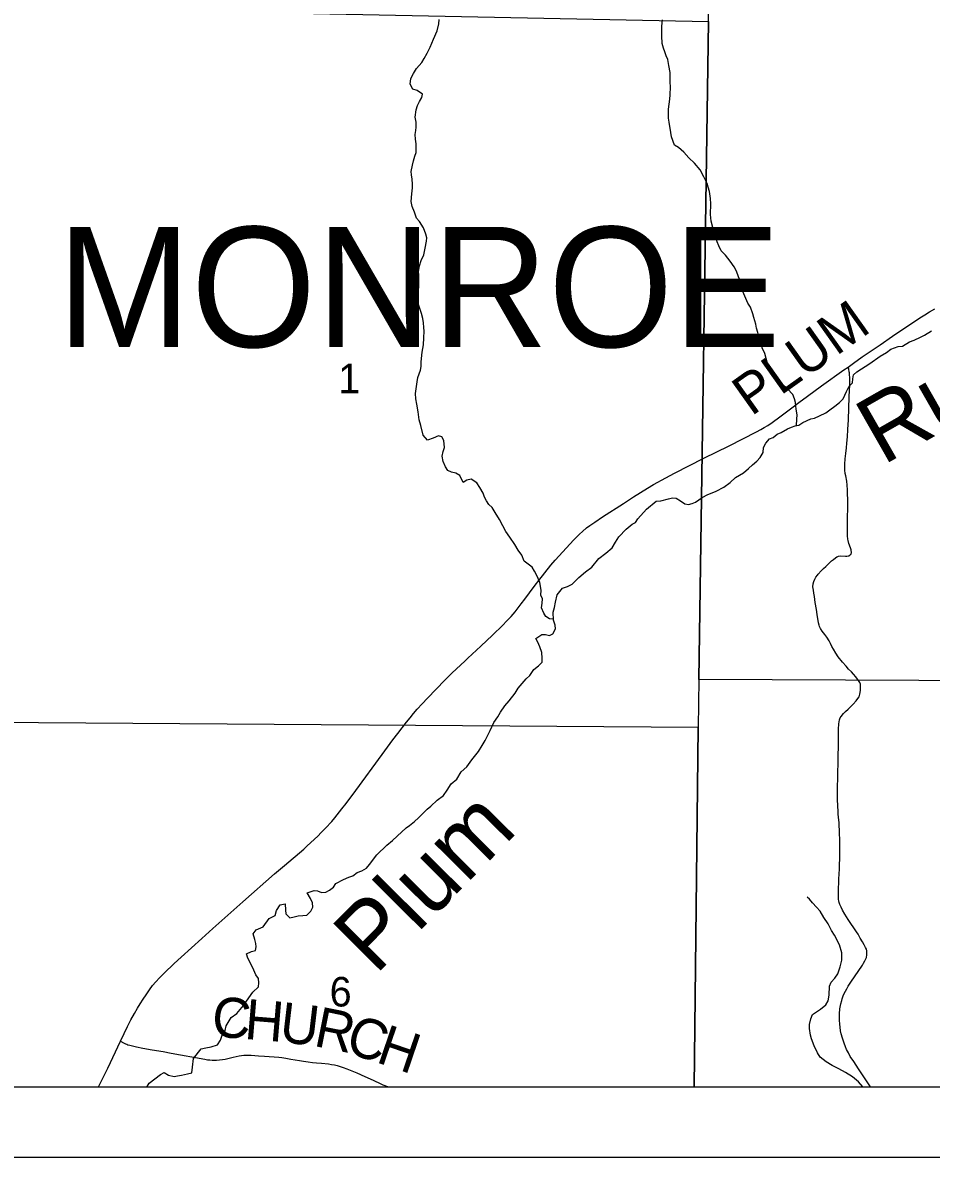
# Model space of a CAD drawing. Extents: x -1.2 to 34, y -8.5 to 22.
# Drawn here: x 4.454 to 5.742, y 14 to 15.609 of the extents above; entities that cross this region are included whole.
import ezdxf

# ---------------------------------------------------------------- set-up
doc = ezdxf.new("R2010")
doc.units = 0
for name, color, linetype in [('GM_X_County_Road', 7, 'Continuous'), ('GM_X_County_Road_Text', 7, 'Continuous'), ('GM_X_Minor_River', 7, 'Continuous'), ('GM_X_Minor_River_Text', 7, 'Continuous'), ('GM_X_Section', 7, 'Continuous'), ('GM_X_Section_Text', 7, 'Continuous'), ('GM_X_Township_Road', 7, 'Continuous'), ('GM_X_Township_Road_Text', 7, 'Continuous'), ('GM_X_Township_Text', 7, 'Continuous'), ('GM_X_Unincorporated_Text', 7, 'Continuous'), ('SH_Cut_Line', 7, 'Continuous'), ('SH_Data', 7, 'Continuous')]:
    doc.layers.add(name, color=color, linetype=linetype)

msp = doc.modelspace()

# ---------------------------------------------------------------- linework, layer by layer
at = {"layer": 'GM_X_County_Road'}
for points in [[(4.5926, 14.1646), (4.5978, 14.1754), (4.6025, 14.1852), (4.6072, 14.1947), (4.6122, 14.2039), (4.6164, 14.2112), (4.6203, 14.2178), (4.6246, 14.2243), (4.6288, 14.2305), (4.6335, 14.2373), (4.638, 14.2434), (4.6426, 14.2488), (4.6478, 14.2542), (4.6543, 14.261), (4.6687, 14.2749), (4.6782, 14.2837), (4.7078, 14.3103), (4.7234, 14.3246), (4.7661, 14.3622), (4.8108, 14.4017), (4.825, 14.4136), (4.8526, 14.4371), (4.8567, 14.441), (4.8725, 14.4559), (4.8767, 14.4602), (4.883, 14.4667), (4.8919, 14.4762), (4.8963, 14.4813), (4.9065, 14.4939), (4.9126, 14.5018), (4.9261, 14.52), (4.9637, 14.5712), (4.9788, 14.5917), (4.9856, 14.6008), (4.9982, 14.6168), (5.0031, 14.6232), (5.0079, 14.6293), (5.0131, 14.6353), (5.0202, 14.6428), (5.0278, 14.6509), (5.0525, 14.6766), (5.0623, 14.6864), (5.0813, 14.7041), (5.0851, 14.7076), (5.1033, 14.7245), (5.1198, 14.7401), (5.1345, 14.7543), (5.14, 14.76), (5.1463, 14.7669), (5.152, 14.7734), (5.1565, 14.779), (5.1608, 14.7846), (5.1658, 14.7913), (5.1726, 14.8005), (5.1805, 14.8113), (5.1855, 14.818), (5.2028, 14.8396), (5.2089, 14.8465), (5.2302, 14.87), (5.2349, 14.8751), (5.239, 14.8795), (5.2432, 14.8833), (5.2474, 14.8873), (5.2535, 14.8923), (5.2581, 14.8958), (5.2649, 14.9005), (5.276, 14.9079), (5.3056, 14.9272), (5.3201, 14.9364), (5.3399, 14.9489), (5.3484, 14.9539), (5.3656, 14.9634), (5.3781, 14.9699), (5.4199, 14.9911), (5.4557, 15.009), (5.4944, 15.0285), (5.5006, 15.0318), (5.5053, 15.0346), (5.5105, 15.0378), (5.5165, 15.0419), (5.5276, 15.0498), (5.5426, 15.0614), (5.5545, 15.0703), (5.5667, 15.079), (5.5866, 15.0937), (5.6181, 15.1163), (5.6243, 15.1204), (5.6319, 15.126), (5.6444, 15.1348), (5.6697, 15.1521), (5.6872, 15.1643), (5.7088, 15.1787), (5.7185, 15.1852), (5.7258, 15.1902), (5.7329, 15.1947), (5.7397, 15.1987), (5.7472, 15.2028)], [(4.5614, 14.1), (4.5743, 14.1262), (4.5926, 14.1646)]]:
    msp.add_lwpolyline(points, dxfattribs=at)
at = {"layer": 'GM_X_Minor_River'}
for points in [[(5.0104, 15.4504), (5.0111, 15.4557), (5.0118, 15.4607), (5.0117, 15.4675), (5.0105, 15.4747), (5.0115, 15.4854), (5.0136, 15.4915), (5.0162, 15.4969), (5.0199, 15.5027), (5.0206, 15.5076), (5.0129, 15.5128), (5.0069, 15.5147), (5.003, 15.5214), (5.004, 15.5298), (5.008, 15.5368), (5.0121, 15.544), (5.0199, 15.5522), (5.0229, 15.5579), (5.0273, 15.5656), (5.0317, 15.574), (5.0365, 15.5855), (5.0416, 15.5974), (5.0437, 15.6073), (5.0444, 15.6131)], [(5.5513, 15.0374), (5.5517, 15.0465), (5.552, 15.0526), (5.5508, 15.0609), (5.5495, 15.07), (5.5483, 15.0754), (5.5459, 15.0814), (5.5382, 15.0897), (5.5302, 15.0964), (5.5206, 15.1031), (5.5163, 15.1095), (5.5128, 15.1186), (5.5101, 15.1254), (5.5061, 15.1398), (5.5025, 15.1477), (5.5001, 15.1584), (5.4978, 15.164), (5.4962, 15.1693), (5.4946, 15.1754), (5.4933, 15.1811), (5.4921, 15.186), (5.4905, 15.1909), (5.4893, 15.1959), (5.4858, 15.2053), (5.4819, 15.211), (5.478, 15.2212), (5.4752, 15.2276), (5.4724, 15.2398), (5.4689, 15.2485), (5.4661, 15.2564), (5.4626, 15.2628), (5.4572, 15.2707), (5.4506, 15.279), (5.4441, 15.2854), (5.441, 15.2922), (5.4386, 15.2979), (5.4355, 15.3073), (5.4323, 15.3183), (5.4302, 15.3274), (5.429, 15.3369), (5.4295, 15.3518), (5.429, 15.3597), (5.4277, 15.3692), (5.4258, 15.3753), (5.4245, 15.3806), (5.4199, 15.3901), (5.4144, 15.3999), (5.4063, 15.4096), (5.3986, 15.4171), (5.3913, 15.425), (5.3837, 15.4318), (5.3783, 15.4351), (5.374, 15.4468), (5.3728, 15.4529), (5.3706, 15.4677), (5.3698, 15.4734), (5.3696, 15.4863), (5.3713, 15.5001), (5.372, 15.5066), (5.3726, 15.518), (5.3721, 15.5244), (5.3719, 15.5381), (5.3702, 15.548), (5.3686, 15.5564), (5.3662, 15.5617), (5.3643, 15.5673), (5.3623, 15.5726), (5.3607, 15.5791), (5.3602, 15.5901), (5.36, 15.5981), (5.3603, 15.6038), (5.361, 15.6126)], [(5.2063, 14.763), (5.2007, 14.7636), (5.1957, 14.7666), (5.193, 14.7715), (5.1895, 14.7791), (5.1905, 14.7856), (5.1908, 14.792), (5.1885, 14.7969), (5.1891, 14.8042), (5.1871, 14.8148), (5.1835, 14.8239), (5.1797, 14.8311), (5.1762, 14.8367), (5.1704, 14.8408), (5.1651, 14.8453), (5.1615, 14.8536), (5.1565, 14.8608), (5.1515, 14.8687), (5.1445, 14.8792), (5.1391, 14.8871), (5.1344, 14.8951), (5.1297, 14.9045), (5.1239, 14.9143), (5.1197, 14.9211), (5.1147, 14.9256), (5.1116, 14.9309), (5.1085, 14.9358), (5.1065, 14.9418), (5.1018, 14.9498), (5.0976, 14.9565), (5.0899, 14.9614), (5.0835, 14.9601), (5.0782, 14.9566), (5.0736, 14.9665), (5.0678, 14.9702), (5.0617, 14.9712), (5.0568, 14.9738), (5.0533, 14.9791), (5.0498, 14.9866), (5.0485, 14.9942), (5.05, 15.0007), (5.0518, 15.0065), (5.0509, 15.0163), (5.0481, 15.0213), (5.0432, 15.0231), (5.0357, 15.0195), (5.0278, 15.0168), (5.0216, 15.0239), (5.0184, 15.0375), (5.016, 15.0455), (5.0147, 15.0569), (5.0126, 15.0679), (5.0114, 15.0755), (5.0109, 15.0831), (5.0133, 15.0995), (5.0143, 15.1056), (5.018, 15.1159), (5.0187, 15.1213), (5.0189, 15.1278), (5.0203, 15.1415), (5.022, 15.1518), (5.0226, 15.1617), (5.0229, 15.1712), (5.0228, 15.1765), (5.0223, 15.183), (5.0211, 15.1894), (5.0191, 15.1966), (5.0151, 15.2091), (5.0128, 15.2141), (5.013, 15.2209), (5.0152, 15.2282), (5.0155, 15.2354), (5.0153, 15.251), (5.0152, 15.256), (5.0166, 15.264), (5.0187, 15.2716), (5.0224, 15.2797), (5.0245, 15.2892), (5.0263, 15.2988), (5.0266, 15.3037), (5.0254, 15.309), (5.0222, 15.3177), (5.0164, 15.3268), (5.0122, 15.3317), (5.0094, 15.34), (5.0059, 15.3483), (5.0046, 15.3551), (5.0056, 15.3662), (5.0066, 15.3746), (5.0066, 15.3799), (5.0061, 15.3871), (5.0049, 15.3928), (5.0044, 15.3978), (5.0065, 15.4066), (5.008, 15.4127), (5.0098, 15.4195), (5.0116, 15.4245), (5.0119, 15.4295), (5.0118, 15.4371), (5.0109, 15.4435), (5.0104, 15.4504)], [(5.271, 14.8492), (5.2808, 14.8566), (5.2897, 14.8643), (5.2942, 14.872), (5.299, 14.8797), (5.3094, 14.8905), (5.318, 14.8975), (5.3229, 14.9002), (5.3262, 14.9052), (5.3385, 14.9188), (5.352, 14.9304), (5.3588, 14.9309), (5.3697, 14.9337), (5.3754, 14.9349), (5.3803, 14.9346), (5.3864, 14.9309), (5.3929, 14.9264), (5.3979, 14.9254), (5.4032, 14.927), (5.408, 14.929), (5.4174, 14.9356), (5.4253, 14.9399), (5.4317, 14.9419), (5.4374, 14.9446), (5.4479, 14.9501), (5.4569, 14.9567), (5.4647, 14.9641), (5.476, 14.9707), (5.4831, 14.9765), (5.4887, 14.9816), (5.495, 14.987), (5.4995, 14.992), (5.5036, 14.9993), (5.5042, 15.0062), (5.5075, 15.0127), (5.5128, 15.0185), (5.518, 15.0208), (5.5236, 15.0251), (5.5293, 15.0279), (5.5383, 15.033), (5.5439, 15.0353), (5.5492, 15.0369), (5.5545, 15.0382), (5.5601, 15.042), (5.5714, 15.0472), (5.5767, 15.048), (5.5838, 15.0515), (5.5925, 15.0555), (5.5985, 15.0598), (5.6056, 15.0652), (5.612, 15.0702), (5.6172, 15.0753), (5.622, 15.0856), (5.626, 15.0933), (5.6305, 15.0983), (5.6312, 15.1036), (5.6318, 15.1094), (5.6367, 15.1136), (5.6551, 15.1253), (5.6697, 15.1358), (5.6787, 15.1413), (5.6851, 15.1456), (5.6952, 15.1495), (5.7013, 15.15), (5.7114, 15.1563), (5.7182, 15.1586), (5.7272, 15.163), (5.7325, 15.1657), (5.7426, 15.1716)], [(4.7813, 14.2654), (4.7774, 14.2745), (4.7731, 14.2821), (4.7711, 14.2885), (4.7782, 14.292), (4.7839, 14.2933), (4.785, 14.2982), (4.7845, 14.3032), (4.7829, 14.3089), (4.7805, 14.3168), (4.785, 14.3226), (4.7948, 14.3269), (4.8033, 14.3385), (4.8116, 14.3428), (4.8134, 14.3497), (4.8189, 14.3581), (4.8261, 14.3594), (4.8262, 14.3506), (4.8271, 14.3453), (4.8324, 14.3397), (4.8389, 14.3409), (4.8445, 14.3422), (4.851, 14.3426), (4.8566, 14.3431), (4.8622, 14.3489), (4.8652, 14.3547), (4.8647, 14.3607), (4.862, 14.3668), (4.8573, 14.3751), (4.8671, 14.3783), (4.872, 14.378), (4.8774, 14.3754), (4.8838, 14.3759), (4.889, 14.3786), (4.8943, 14.3829), (4.8976, 14.3883), (4.9085, 14.3941), (4.9164, 14.3973), (4.9217, 14.3989), (4.928, 14.404), (4.9345, 14.406), (4.9412, 14.4099), (4.9457, 14.4149), (4.9561, 14.4287), (4.9699, 14.4427), (4.9781, 14.4493), (4.9849, 14.4551), (4.9976, 14.4671), (5.0024, 14.4702), (5.0092, 14.476), (5.0151, 14.4814), (5.0271, 14.4934), (5.0327, 14.4977), (5.0413, 14.5062), (5.0506, 14.5132), (5.0555, 14.5205), (5.0614, 14.5293), (5.0692, 14.5359), (5.0755, 14.5467), (5.0837, 14.5536), (5.0908, 14.5637), (5.1001, 14.5752), (5.1053, 14.584), (5.1097, 14.591), (5.1134, 14.5986), (5.1167, 14.6052), (5.1218, 14.6163), (5.1274, 14.6243), (5.1315, 14.6309), (5.1374, 14.6401), (5.1437, 14.6471), (5.1519, 14.6582), (5.1563, 14.6651), (5.1679, 14.6783), (5.1727, 14.6829), (5.1787, 14.6914), (5.1854, 14.6968), (5.1903, 14.7018), (5.1902, 14.7075), (5.1897, 14.7159), (5.1869, 14.7238), (5.1842, 14.7303), (5.1814, 14.7356), (5.1897, 14.7414), (5.195, 14.7411), (5.2007, 14.7397), (5.2056, 14.7424), (5.2092, 14.7493), (5.2088, 14.7546), (5.2064, 14.7614), (5.2059, 14.7728), (5.2077, 14.7797), (5.2095, 14.787), (5.2116, 14.7973), (5.2194, 14.8069), (5.2265, 14.8093), (5.2329, 14.8128), (5.2426, 14.8221), (5.252, 14.8303), (5.261, 14.8369), (5.271, 14.8492)], [(5.6452, 14.1), (5.6389, 14.107), (5.6305, 14.1141), (5.6205, 14.1204), (5.611, 14.1256), (5.6018, 14.13), (5.5931, 14.1352), (5.5846, 14.1419), (5.5811, 14.1483), (5.5761, 14.1581), (5.5725, 14.168), (5.5709, 14.1733), (5.5696, 14.1828), (5.5696, 14.1881), (5.5713, 14.1961), (5.5739, 14.2023), (5.5851, 14.21), (5.5926, 14.2162), (5.596, 14.2216), (5.5973, 14.23), (5.5979, 14.2426), (5.6005, 14.2483), (5.6057, 14.2541), (5.6098, 14.2603), (5.613, 14.2702), (5.6152, 14.2794), (5.6155, 14.2843), (5.6154, 14.2901), (5.6122, 14.3014), (5.6052, 14.315), (5.6009, 14.3214), (5.5959, 14.3309), (5.5901, 14.3399), (5.5846, 14.349), (5.5796, 14.3546), (5.5739, 14.361), (5.5696, 14.3662), (5.5664, 14.3687)], [(4.63, 14.1), (4.63, 14.1002), (4.6329, 14.1052), (4.649, 14.1173), (4.6543, 14.12), (4.6604, 14.1163), (4.6684, 14.1145), (4.6733, 14.1153), (4.679, 14.1166), (4.6876, 14.1182), (4.6937, 14.1195), (4.6943, 14.1278), (4.696, 14.1401), (4.7068, 14.1539), (4.7136, 14.1552), (4.7212, 14.1564), (4.7298, 14.1592), (4.7343, 14.1661), (4.7372, 14.1746), (4.7409, 14.1799), (4.7423, 14.1864), (4.7493, 14.198), (4.7572, 14.2038), (4.7669, 14.2154), (4.7713, 14.2215), (4.7802, 14.2342), (4.7881, 14.2419), (4.7887, 14.2473), (4.7883, 14.2534), (4.7844, 14.2586), (4.7813, 14.2654)]]:
    msp.add_lwpolyline(points, dxfattribs=at)
at = {"layer": 'GM_X_Section'}
for points in [[(6.2657, 15.6908), (6.2441, 14.6736), (5.4125, 14.6774), (5.4262, 15.6104), (5.428, 15.6979)], [(4.4223, 15.6306), (5.4262, 15.6104), (5.4125, 14.6774), (5.4116, 14.6095), (4.409, 14.6166)], [(5.4061, 14.1), (6.2289, 14.1), (6.2441, 14.6736), (5.4125, 14.6774), (5.4116, 14.6095)], [(4.3964, 14.1), (5.4061, 14.1), (5.4116, 14.6095), (4.409, 14.6166)]]:
    msp.add_lwpolyline(points, close=True, dxfattribs=at)
at = {"layer": 'GM_X_Township_Road'}
for points in [[(5.6236, 14.9005), (5.6237, 14.9271), (5.6234, 14.9464), (5.623, 14.9528), (5.6224, 14.9585), (5.6209, 14.9664), (5.6203, 14.9694), (5.6196, 14.9741), (5.6195, 14.9759), (5.6197, 14.9828), (5.6202, 14.9905), (5.6211, 14.9978), (5.622, 15.0061), (5.6226, 15.0124), (5.6233, 15.0216), (5.624, 15.0318), (5.6247, 15.0458), (5.6259, 15.0782), (5.6266, 15.0958), (5.6268, 15.1026), (5.6262, 15.1122), (5.6259, 15.1139), (5.6253, 15.1173), (5.6243, 15.1204)], [(5.6134, 14.3564), (5.6125, 14.3584), (5.6116, 14.3613), (5.6111, 14.3634), (5.6108, 14.3657), (5.6106, 14.3681), (5.6108, 14.3824), (5.611, 14.3883), (5.6112, 14.3942), (5.6116, 14.4019), (5.6119, 14.4085), (5.6122, 14.4157), (5.6125, 14.4228), (5.6126, 14.4287), (5.6128, 14.4453), (5.6122, 14.4645), (5.6118, 14.4697), (5.6114, 14.4749), (5.6108, 14.4819), (5.6104, 14.4868), (5.6101, 14.4914), (5.6099, 14.4974), (5.6094, 14.5081), (5.6091, 14.5198), (5.6097, 14.5434), (5.61, 14.5611), (5.6106, 14.591), (5.6107, 14.6071), (5.6113, 14.6147), (5.6118, 14.6176), (5.6123, 14.6201), (5.6132, 14.6229), (5.6145, 14.625), (5.618, 14.6294), (5.6205, 14.6319), (5.6245, 14.6354), (5.6316, 14.6426), (5.6356, 14.647), (5.6382, 14.6507), (5.6398, 14.6531), (5.6411, 14.6567), (5.6418, 14.6617), (5.642, 14.6653), (5.6417, 14.6706), (5.6409, 14.673), (5.6401, 14.6745), (5.6376, 14.678), (5.6354, 14.681), (5.632, 14.6849), (5.6291, 14.6882), (5.625, 14.6921), (5.6215, 14.6962), (5.6164, 14.7021), (5.6104, 14.7097), (5.6071, 14.7146), (5.6037, 14.7203), (5.6014, 14.7243), (5.5995, 14.7283), (5.5973, 14.7322), (5.5941, 14.7375), (5.5912, 14.7414), (5.5873, 14.7461), (5.5851, 14.7499), (5.5838, 14.7525), (5.5831, 14.7547), (5.5823, 14.7578), (5.5805, 14.7696), (5.5793, 14.7769), (5.5776, 14.7865), (5.5764, 14.795), (5.5755, 14.7998), (5.575, 14.8039), (5.5745, 14.8088), (5.5748, 14.8131), (5.5757, 14.8164), (5.577, 14.8195), (5.5786, 14.8224), (5.5809, 14.8255), (5.5818, 14.8267), (5.5862, 14.8315), (5.5896, 14.8347), (5.5927, 14.8377), (5.5973, 14.8423), (5.6009, 14.8456), (5.6036, 14.8478), (5.6063, 14.8499), (5.6082, 14.8512), (5.6098, 14.8519), (5.6107, 14.8523), (5.6135, 14.8526), (5.6206, 14.8524), (5.6226, 14.8523), (5.6246, 14.8526), (5.6257, 14.853), (5.6272, 14.854), (5.628, 14.8549), (5.6286, 14.856), (5.6289, 14.8572), (5.6286, 14.8611), (5.6281, 14.8628), (5.6262, 14.8679), (5.6254, 14.8702), (5.6243, 14.8747), (5.624, 14.8764), (5.6236, 14.8813), (5.6235, 14.8855), (5.6236, 14.8995), (5.6236, 14.9005)], [(5.656, 14.1), (5.6389, 14.1254), (5.6322, 14.1356), (5.6274, 14.1431), (5.6247, 14.148), (5.6222, 14.1528), (5.6205, 14.1568), (5.6187, 14.1616), (5.6162, 14.1691), (5.6146, 14.1751), (5.6137, 14.1795), (5.613, 14.1843), (5.6125, 14.1887), (5.6121, 14.1945), (5.612, 14.2007), (5.6121, 14.2033), (5.6128, 14.2105), (5.6132, 14.213), (5.6141, 14.2175), (5.6152, 14.2223), (5.6158, 14.2245), (5.6175, 14.2291), (5.6189, 14.2321), (5.6224, 14.239), (5.6246, 14.2427), (5.6282, 14.2483), (5.6446, 14.2723), (5.6463, 14.2751), (5.6482, 14.2785), (5.6492, 14.2805), (5.6502, 14.2835), (5.6509, 14.287), (5.651, 14.2895), (5.6507, 14.2929), (5.6502, 14.2953), (5.6491, 14.2975), (5.6472, 14.301), (5.6446, 14.3056), (5.6414, 14.3108), (5.6384, 14.3163), (5.6363, 14.3195), (5.6245, 14.3371), (5.6197, 14.3447), (5.6164, 14.3505), (5.6144, 14.3545), (5.6134, 14.3564)], [(4.5926, 14.1646), (4.5968, 14.1622), (4.5994, 14.161), (4.6012, 14.1603), (4.6029, 14.1596), (4.6054, 14.1589), (4.6095, 14.1578), (4.6149, 14.1566), (4.624, 14.1548), (4.6375, 14.1524), (4.6529, 14.1498), (4.6644, 14.1478), (4.7118, 14.1392), (4.7157, 14.1384), (4.7189, 14.138), (4.7225, 14.1377), (4.7258, 14.1376), (4.7285, 14.1377), (4.733, 14.1381), (4.7369, 14.1386), (4.741, 14.1393), (4.7463, 14.1405), (4.752, 14.1419), (4.7609, 14.1439), (4.7642, 14.1444), (4.7674, 14.1448), (4.7715, 14.1449), (4.7775, 14.1447), (4.7831, 14.1443), (4.7883, 14.1438), (4.7966, 14.1432), (4.8033, 14.143), (4.8104, 14.1424), (4.8168, 14.1418), (4.8212, 14.1414), (4.8268, 14.1405), (4.8339, 14.1392), (4.8402, 14.1381), (4.8462, 14.1371), (4.8517, 14.1363), (4.8587, 14.1353), (4.8645, 14.1346), (4.8705, 14.1339), (4.8776, 14.1333), (4.8873, 14.1323), (4.8918, 14.1317), (4.896, 14.131), (4.8999, 14.13), (4.904, 14.1289), (4.9083, 14.1275), (4.9133, 14.1256), (4.9181, 14.1237), (4.9276, 14.1197), (4.9387, 14.1147), (4.9507, 14.1091), (4.9614, 14.1043), (4.9646, 14.1029), (4.9711, 14.1004), (4.9723, 14.1)]]:
    msp.add_lwpolyline(points, dxfattribs=at)
at = {"layer": 'GM_X_Unincorporated_Text'}
msp.add_line((2.3586, 14.1), (8.2551, 14.1), dxfattribs=at)
at = {"layer": 'SH_Cut_Line'}
msp.add_lwpolyline([(2.3586, 14.1), (8.9, 14.1), (8.9, 17.6758), (8.3326, 17.6871), (7.9782, 17.6941), (7.8111, 17.6977), (7.3722, 17.707), (7.1254, 17.7122), (6.7322, 17.7204), (6.6751, 17.7216), (6.665, 17.7216)], dxfattribs=at)
at = {"layer": 'SH_Data'}
for p, q in [((2.1, 14.1), (8.9, 14.1)), ((2.1, 14.1), (8.9, 14.1)), ((2, 14), (9, 14)), ((2, 14), (9, 14))]:
    msp.add_line(p, q, dxfattribs=at)

# ---------------------------------------------------------------- texts
at = {"layer": 'GM_X_County_Road_Text'}
msp.add_text('PLUM', height=0.05682, rotation=35.375, dxfattribs=at).set_placement((5.4869, 15.0499))
at = {"layer": 'GM_X_Minor_River_Text'}
for s, rotation, p in [('Run', 29.6968, (5.6736, 14.9804)), ('Plum', 45.2251, (4.954, 14.2573))]:
    msp.add_text(s, height=0.09469, rotation=rotation, dxfattribs=at).set_placement(p)
at = {"layer": 'GM_X_Section_Text'}
for s, p in [('1', (4.9011, 15.0834)), ('6', (4.889, 14.2138))]:
    msp.add_text(s, height=0.0419, rotation=0, dxfattribs=at).set_placement(p)
at = {"layer": 'GM_X_Township_Road_Text'}
for s, rotation, p in [('C', 355.7028, (4.7206, 14.1715)), ('H', 355.2554, (4.767, 14.168)), ('U', 353.2491, (4.8163, 14.1639)), ('R', 348.5867, (4.8648, 14.1582)), ('C', 342.3587, (4.909, 14.1494)), ('H', 341.2229, (4.9531, 14.1353))]:
    msp.add_text(s, height=0.0568, rotation=rotation, dxfattribs=at).set_placement(p)
at = {"layer": 'GM_X_Township_Text'}
msp.add_text('MONROE', height=0.17045, rotation=0, dxfattribs=at).set_placement((4.5026, 15.1488))

doc.saveas('drawing.dxf')
